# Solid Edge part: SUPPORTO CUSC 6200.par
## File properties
Subject: SUPPORTO CUSC 6200
Author: f_grande
Template: Normal.par
Last saved by: f_grande
Revision: 4
Application: Solid Edge
Material: Plexiglas opalino
Stile della faccia: Bianco (vetro)
Stile di riempimento: ANSI34(Plastica)
Stile virtuale: Marroncino (lucido)
Coef. of Thermal Exp: 0.0
Thermal Conductivity: 1.5
Specific Heat: 0.0
Modulus of Elasticity: 2757902.8
Poisson's Ratio: 0.4
Yield Stress: 6894757.0
Ultimate Stress: 0.0
Elongation: 0.0
Tipo di contenuto documento: 0
Densità: 1385,000 kg/m^3
Precisione: 0,990
Document Number: KR0130
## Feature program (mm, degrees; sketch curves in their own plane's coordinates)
sketch for "unnamed Protrusion 1" plane through (0, 0, 0) normal (0, -1, 0) x-axis (1, 0, 0)
  line (-35.0443, 29.8388) -> (19.9557, 29.8388)
  line (19.9557, 29.8388) -> (19.9557, -25.1612)
  line (19.9557, -25.1612) -> (-35.0443, -25.1612)
  line (-35.0443, -25.1612) -> (-35.0443, 29.8388)
  dimension (linear) = 35.0443
  dimension (linear) = 35.0443
extrude "unnamed Protrusion 1" add finite 12 along +normal
sketch for "Foro_1" plane through (-7.5443, -12, 2.3388) normal (0, -1, 0) x-axis (1, 0, 0)
  hole centre (0, 0) bore radius 15
hole "Foro_1" diameter 30 finite
sketch for "Foro_2" plane through (-7.5443, 0, 2.3388) normal (0, 1, 0) x-axis (-1, 0, 0)
  hole centre (23.57, 23.57) bore radius 2.5
hole "Foro_2" diameter 5 through
sketch for "unnamed Hole 1" plane through (-7.5443, 0, 2.3388) normal (0, 1, 0) x-axis (-1, 0, 0)
  hole centre (23.57, -23.57) bore radius 2.5
hole "unnamed Hole 1" through
sketch for "unnamed Hole 2" plane through (-7.5443, 0, 2.3388) normal (0, 1, 0) x-axis (-1, 0, 0)
  hole centre (-23.57, -23.57) bore radius 2.5
hole "unnamed Hole 2" through
sketch for "unnamed Hole 3" plane through (-7.5443, 0, 2.3388) normal (0, 1, 0) x-axis (-1, 0, 0)
  hole centre (-23.57, 23.57) bore radius 2.5
hole "unnamed Hole 3" through
pattern "unnamed Pattern 1" of "Foro_2", "unnamed Hole 1", "unnamed Hole 2", "unnamed Hole 3"
sketch for "Foro_6" plane through (-7.5443, -1, 2.3388) normal (0, -1, 0) x-axis (1, 0, 0)
  hole centre (0, 0) bore radius 10
hole "Foro_6" diameter 20 through
sketch for "Foro_7" plane through (-7.5443, -6, -25.1612) normal (0, 0, -1) x-axis (0, -1, 0)
hole "Foro_7" diameter 5 through
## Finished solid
Body 1: solid body, 15 faces, 28 edges, 8 vertices.
  Faces by surface: cylinder 8, plane 7
  Edges by curve: circle 14, line 12, intersection 2
Bounding box of the edges (mm): 55.000 x 12.000 x 55.000, from (-35.0443, -12, -25.1612) to (19.9557, 0, 29.8388).
Cylindrical faces by radius (mm): R2.067 x2, R2.5 x4, R10 x1, R15 x1
Planar faces by outward normal: +x 1, +y 1, +z 1, -x 1, -y 2, -z 1
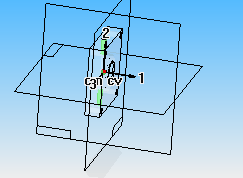
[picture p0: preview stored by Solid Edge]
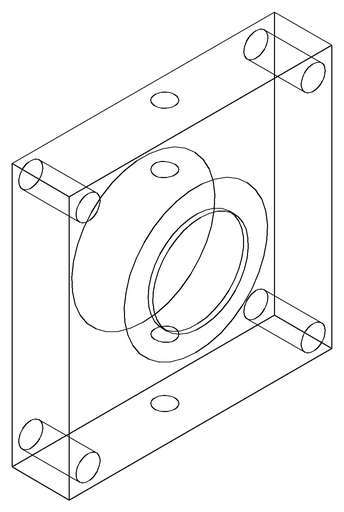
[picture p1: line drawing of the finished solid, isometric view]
